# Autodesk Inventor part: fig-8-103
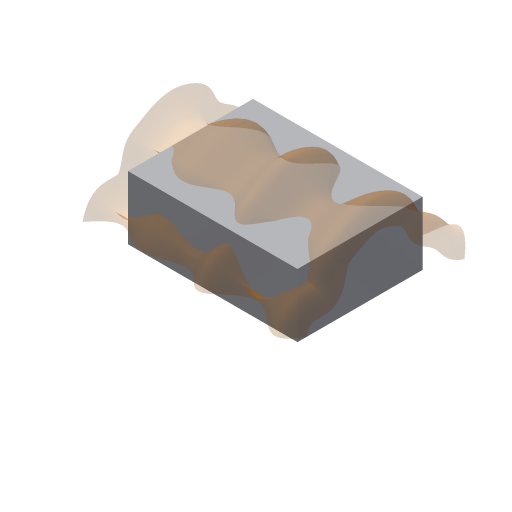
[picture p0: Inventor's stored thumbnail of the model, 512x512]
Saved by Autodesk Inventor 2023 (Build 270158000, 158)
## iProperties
Part Number: fig-8-103
Document SubType Name: Modeling
Created: 2002-12
Designer: deepak
Density: 1 g/cm^3
Material: Generic
Appearance: Aluminum - Flat
Control State: 0
Master: False
Checked Out: False
Shininess: 64.0
Length Units: 11269
Angle Units: 11279
Time Units: 11290
Mass Units: 11283
Length Display Precision: 3
Angle Display Precision: 2
Compacted: True
Density: 0.0
Volumn: 0.0
Area: 0.0
PropertySet Name: Model Information
Author: deepak
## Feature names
1. Extrusion1
## Parameters: d0 = 25 mm, d1 = 0, d2 = 0, d3 = 0
